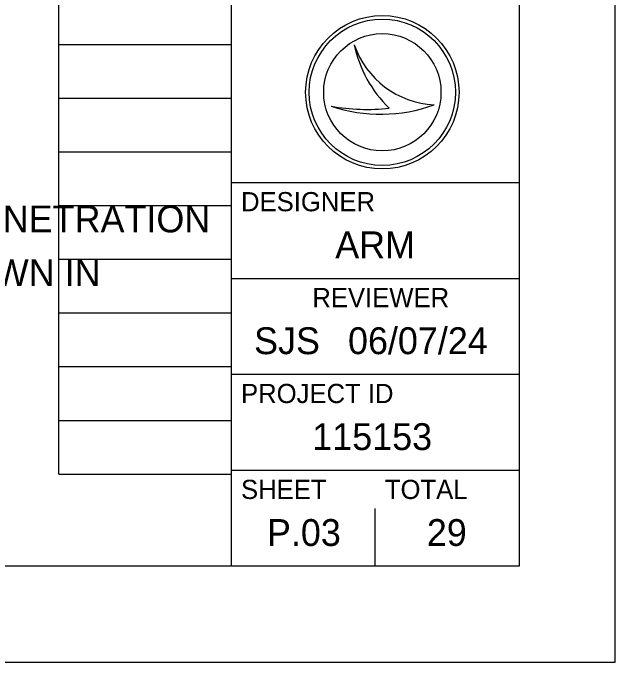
# Model space of a CAD drawing. Extents: x 0 to 34, y 0 to 22.
# Drawn here: x 30.861 to 34, y 0 to 3.384 of the extents above; entities that cross this region are included whole.
import ezdxf

# ---------------------------------------------------------------- set-up
doc = ezdxf.new("R2010")
doc.units = 0
for name, color, linetype in [('SH_Border', 7, 'Continuous'), ('SH_Cut_Line', 7, 'Continuous'), ('SH_Data', 7, 'Continuous'), ('SH_Text', 7, 'Continuous')]:
    doc.layers.add(name, color=color, linetype=linetype)

msp = doc.modelspace()

# ---------------------------------------------------------------- linework, layer by layer
at = {"layer": 'SH_Border'}
for p, q in [((32, 0.5), (32, 21.5)), ((32, 2.5), (33.5, 2.5)), ((32, 2), (33.5, 2)), ((32, 1.5), (33.5, 1.5)), ((32, 1), (33.5, 1))]:
    msp.add_line(p, q, dxfattribs=at)
msp.add_lwpolyline([(1.5, 21.5), (33.5, 21.5), (33.5, 0.5), (1.5, 0.5)], close=True, dxfattribs=at)
at = {"layer": 'SH_Cut_Line'}
msp.add_lwpolyline([(0, 0), (34, 0), (34, 22), (0, 22)], close=True, dxfattribs=at)
at = {"layer": 'SH_Data'}
for p, q in [((31.1, 0.98), (31.1, 21.14)), ((32, 0.98), (32, 21.14)), ((31.1, 3.22), (32, 3.22)), ((32.6406, 3.218), (32.6406, 3.218)), ((31.1, 2.94), (32, 2.94)), ((32.5204, 2.898), (32.5204, 2.898)), ((33.0565, 2.9052), (33.0565, 2.9052)), ((31.1, 2.66), (32, 2.66)), ((31.1, 2.38), (32, 2.38)), ((31.1, 2.1), (32, 2.1)), ((31.1, 1.82), (32, 1.82)), ((31.1, 1.54), (32, 1.54)), ((31.1, 1.26), (32, 1.26)), ((31.1, 0.98), (32, 0.98)), ((32.75, 0.5), (32.75, 0.8)), ((32.375, 0.675), (32.375, 0.675))]:
    msp.add_line(p, q, dxfattribs=at)
for radius in [0.4, 0.3814, 0.3814, 0.3058]:
    msp.add_circle((32.7867, 2.9704), radius, dxfattribs=at)
for centre, radius, start, end in [((33.0794, 3.3685), 0.4639, 198.9257, 198.9319), ((33.264, 3.3464), 0.6365, 191.6379, 191.6421), ((33.0794, 3.3685), 0.4639, 198.9319, 267.1657), ((33.264, 3.3464), 0.6365, 191.6421, 226.0947), ((32.7051, 3.8938), 1.0128, 259.4964, 259.4995), ((32.7782, 3.6664), 0.8105, 251.4527, 251.4576), ((32.7782, 3.6664), 0.8105, 251.4576, 290.0832), ((32.7051, 3.8938), 1.0128, 259.4995, 276.6672)]:
    msp.add_arc(centre, radius, start, end, dxfattribs=at)

# ---------------------------------------------------------------- texts
for s, height, p in [('DESIGNER', 0.1, (32.05, 2.35)), ('ARM', 0.14, (32.5412, 2.105)), ('REVIEWER', 0.1, (32.4218, 1.85)), ('SJS', 0.14, (32.118, 1.605)), ('06/07/24', 0.14, (32.6078, 1.605)), ('PROJECT ID', 0.1, (32.05, 1.35)), ('115153', 0.14, (32.4215, 1.105)), ('SHEET', 0.1, (32.05, 0.85)), ('TOTAL', 0.1, (32.8, 0.85)), ('P.03', 0.14, (32.1851, 0.605)), ('29', 0.14, (33.0188, 0.605))]:
    msp.add_text(s, height=height, dxfattribs=at).set_placement(p)
at = {"layer": 'SH_Text'}
for s, p in [('PAVEMENT IS EXPECTED TO BE BITUMINOUS CONCRETE OVER PENETRATION ', (24.66, 2.24)), ('MACADAM. REGARDLESS OF MATERIAL FOUND, BACKFILL AS SHOWN IN ', (24.66, 1.96))]:
    msp.add_text(s, height=0.14, dxfattribs=at).set_placement(p)

doc.saveas('drawing.dxf')
